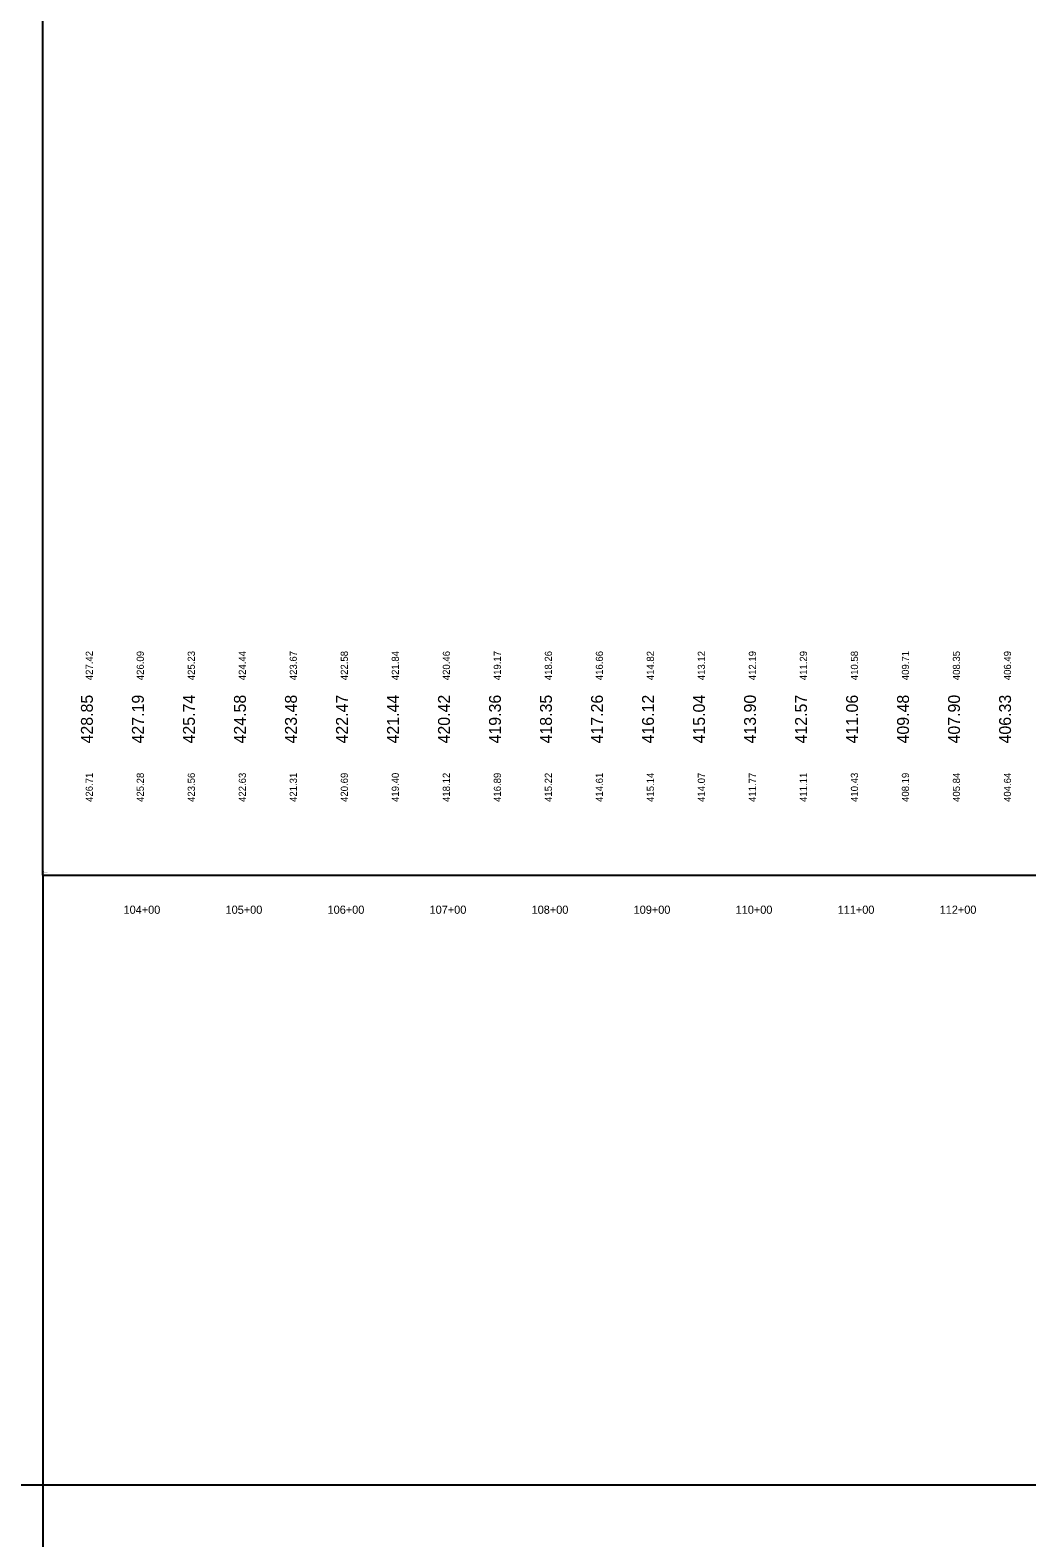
# Model space of a CAD drawing. Extents: x 2084170 to 2089570, y 1072039 to 1077242.
# Drawn here: x 2085177 to 2086154, y 1073890 to 1075367 of the extents above; entities that cross this region are included whole.
import ezdxf

# ---------------------------------------------------------------- set-up
doc = ezdxf.new("R2010")
doc.units = 0
for name, color, linetype in [('RD_DDB_StaTX', 7, 'Continuous'), ('RD_DDB_StripGrade', 7, 'Continuous'), ('RD_GPK_Profile_Cell', 7, 'Continuous'), ('RD_Sketch2', 7, 'Continuous'), ('RD_Sketch3', 7, 'Continuous'), ('RD_Sketch4', 7, 'Continuous')]:
    doc.layers.add(name, color=color, linetype=linetype)

msp = doc.modelspace()

# ---------------------------------------------------------------- linework, layer by layer
at = {"layer": 'RD_GPK_Profile_Cell'}
for q in [(2085189.9, 1077039.2), (2088289.9, 1074539.2), (2085189.9, 1072039.2)]:
    msp.add_line((2085189.9, 1074539.2), q, dxfattribs=at)
at = {"layer": 'RD_Sketch2'}
msp.add_lwpolyline([(2084170, 1073941.9), (2089570, 1073941.9), (2089570, 1077241.9), (2084170, 1077241.9)], close=True, dxfattribs=at)

# ---------------------------------------------------------------- texts
at = {"layer": 'RD_DDB_StaTX'}
for s, p in [('104+00', (2085269, 1074501.4)), ('105+00', (2085369, 1074501.4)), ('106+00', (2085469, 1074501.4)), ('107+00', (2085569, 1074501.4)), ('108+00', (2085669, 1074501.4)), ('109+00', (2085769, 1074501.4)), ('110+00', (2085869, 1074501.4)), ('111+00', (2085969, 1074501.4)), ('112+00', (2086069, 1074501.4))]:
    msp.add_text(s, height=8, dxfattribs=at).set_placement(p)
at = {"layer": 'RD_DDB_StripGrade'}
for s, p in [('428.85', (2085238.9, 1074668.3)), ('427.19', (2085288.9, 1074668.3)), ('425.74', (2085338.9, 1074668.3)), ('424.58', (2085388.9, 1074668.3)), ('423.48', (2085438.9, 1074668.3)), ('422.47', (2085488.9, 1074668.3)), ('421.44', (2085538.9, 1074668.3)), ('420.42', (2085588.9, 1074668.3)), ('419.36', (2085638.9, 1074668.3)), ('418.35', (2085688.9, 1074668.3)), ('417.26', (2085738.9, 1074668.3)), ('416.12', (2085788.9, 1074668.3)), ('415.04', (2085838.9, 1074668.3)), ('413.90', (2085888.9, 1074668.3)), ('412.57', (2085938.9, 1074668.3)), ('411.06', (2085988.9, 1074668.3)), ('409.48', (2086038.9, 1074668.3)), ('407.90', (2086088.9, 1074668.3)), ('406.33', (2086138.9, 1074668.3))]:
    msp.add_text(s, height=11.67, rotation=90, dxfattribs=at).set_placement(p)
at = {"layer": 'RD_GPK_Profile_Cell'}
for s, p in [('181', (2085189.9, 1074542.7)), ('S108', (2085189.9, 1074542.2)), ('10300.000000', (2085189.9, 1074541.7)), ('300', (2085189.9, 1074541.2)), ('100', (2085189.9, 1074540.7)), ('10', (2085189.9, 1074540.2)), ('NOGAP', (2085189.9, 1074539.7))]:
    msp.add_text(s, height=0.5, dxfattribs=at).set_placement(p)
at = {"layer": 'RD_Sketch3'}
for s, p in [('426.71', (2085238.9, 1074611)), ('425.28', (2085288.9, 1074611)), ('423.56', (2085338.9, 1074611)), ('422.63', (2085388.9, 1074611)), ('421.31', (2085438.9, 1074611)), ('420.69', (2085488.9, 1074611)), ('419.40', (2085538.9, 1074611)), ('418.12', (2085588.9, 1074611)), ('416.89', (2085638.9, 1074611)), ('415.22', (2085688.9, 1074611)), ('414.61', (2085738.9, 1074611)), ('415.14', (2085788.9, 1074611)), ('414.07', (2085838.9, 1074611)), ('411.77', (2085888.9, 1074611)), ('411.11', (2085938.9, 1074611)), ('410.43', (2085988.9, 1074611)), ('408.19', (2086038.9, 1074611)), ('405.84', (2086088.9, 1074611)), ('404.64', (2086138.9, 1074611))]:
    msp.add_text(s, height=7, rotation=90, dxfattribs=at).set_placement(p)
at = {"layer": 'RD_Sketch4'}
for s, p in [('427.42', (2085238.9, 1074730.3)), ('426.09', (2085288.9, 1074730.3)), ('425.23', (2085338.9, 1074730.3)), ('424.44', (2085388.9, 1074730.3)), ('423.67', (2085438.9, 1074730.3)), ('422.58', (2085488.9, 1074730.3)), ('421.84', (2085538.9, 1074730.3)), ('420.46', (2085588.9, 1074730.3)), ('419.17', (2085638.9, 1074730.3)), ('418.26', (2085688.9, 1074730.3)), ('416.66', (2085738.9, 1074730.3)), ('414.82', (2085788.9, 1074730.3)), ('413.12', (2085838.9, 1074730.3)), ('412.19', (2085888.9, 1074730.3)), ('411.29', (2085938.9, 1074730.3)), ('410.58', (2085988.9, 1074730.3)), ('409.71', (2086038.9, 1074730.3)), ('408.35', (2086088.9, 1074730.3)), ('406.49', (2086138.9, 1074730.3))]:
    msp.add_text(s, height=7, rotation=90, dxfattribs=at).set_placement(p)

doc.saveas('drawing.dxf')
